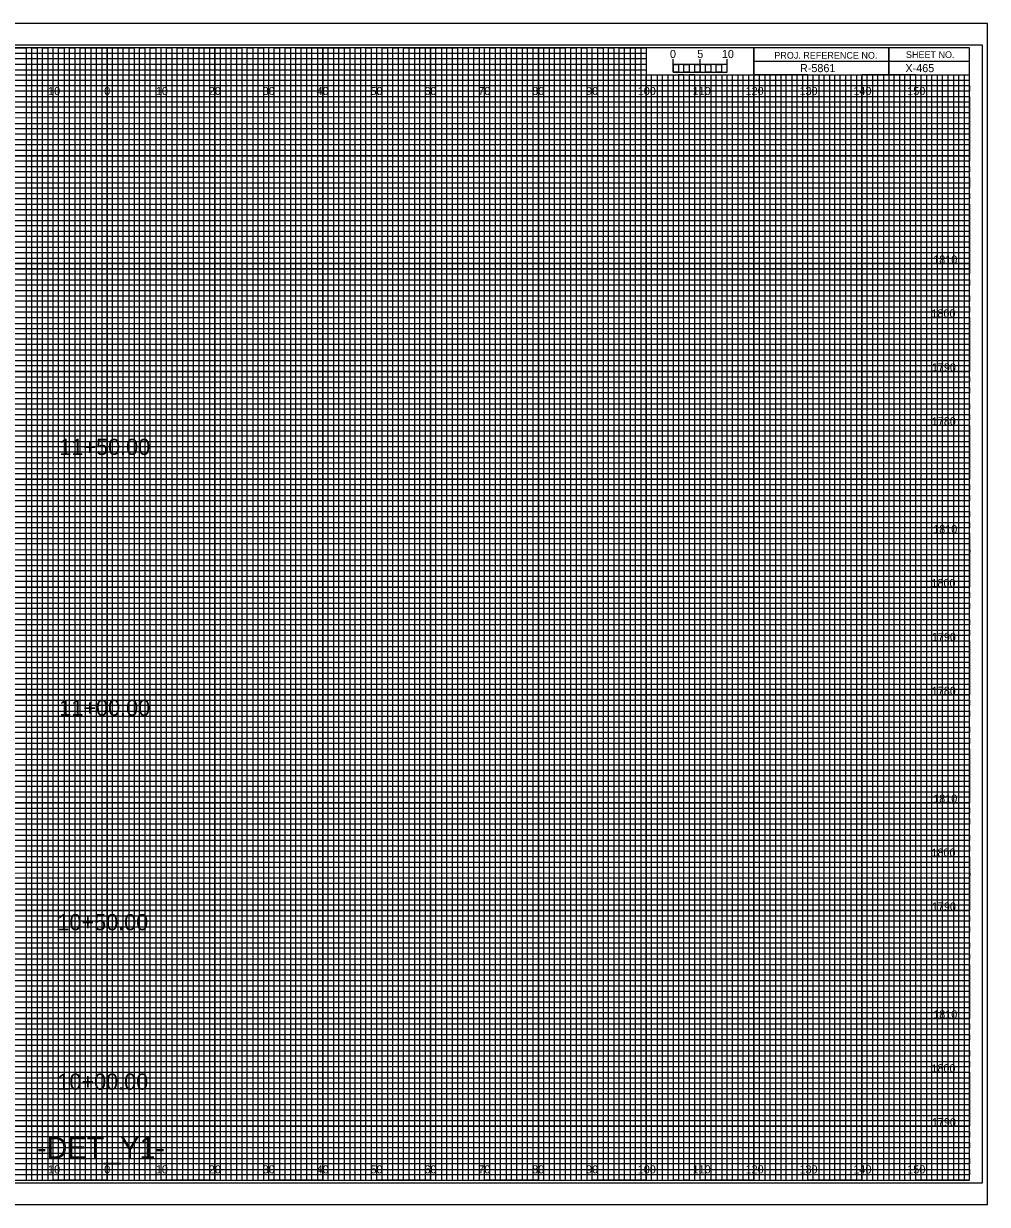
# Model space of a CAD drawing. Extents: x -13 to 323, y -5 to 434.
# Drawn here: x 144.5 to 323.3, y -4.5 to 214.5 of the extents above; entities that cross this region are included whole.
import ezdxf

# ---------------------------------------------------------------- set-up
doc = ezdxf.new("R2010")
doc.units = 0
for name, color, linetype in [('Old_Level_1', 7, 'Continuous'), ('Old_Level_62', 7, 'Continuous'), ('Pattern 1', 7, 'Continuous'), ('Pattern 18', 7, 'Continuous'), ('Pattern 4', 7, 'Continuous'), ('Pattern 5', 7, 'Continuous'), ('Prop Dimension', 7, 'Continuous'), ('Prop Horizontal Alignment', 7, 'Continuous'), ('Prop PHM Label Text', 7, 'Continuous'), ('Prop PHM Label Text White', 7, 'Continuous'), ('Prop PHM Roadway Shape', 7, 'Continuous'), ('Prop PHM White Shape', 7, 'Continuous'), ('Scratch_Level_0', 7, 'Continuous'), ('Scratch_Level_2', 7, 'Continuous'), ('Scratch_Level_3', 7, 'Continuous'), ('Scratch_Level_5', 7, 'Continuous'), ('Scratch_Level_6', 7, 'Continuous')]:
    doc.layers.add(name, color=color, linetype=linetype)

msp = doc.modelspace()

# ---------------------------------------------------------------- linework, layer by layer
at = {"layer": 'Old_Level_62'}
for p, q in [((0, 209), (260, 209)), ((260, 209), (260, 207.98)), ((260, 207.98), (0, 207.98)), ((0, 207), (260, 207)), ((260, 205.89), (0, 205.89)), ((260, 207), (260, 205.89)), ((0, 204), (320, 204))]:
    msp.add_line(p, q, dxfattribs=at)
for points in [[(0, 203), (270, 203), (320, 203), (320, 202), (0, 202)], [(0, 201), (320, 201), (320, 199), (0, 199)], [(0, 198), (320, 198), (320, 197), (0, 196.98)], [(0, 196), (320, 196), (320, 194), (0, 194)], [(0, 193), (320, 193), (320, 192), (0, 192)], [(0, 191), (320, 191), (320, 189), (0, 189)], [(0, 188), (320, 188), (320, 187), (0, 187)], [(0, 186), (320, 186), (320, 184), (0, 184)], [(0, 183), (320, 183), (320, 182), (0, 182)], [(0, 181), (320, 181), (320, 179), (0, 179)], [(0, 178), (320, 178), (320, 177), (0, 177)], [(0, 176), (320, 176), (320, 173.95), (320, 173), (320, 172), (0, 172)], [(0, 174), (320, 174), (320, 173), (0, 173)], [(0, 171), (320, 171), (320, 169), (0, 169.03)], [(0, 169.03), (320, 169), (320, 168), (0, 168)], [(0, 167), (320, 167), (320, 166), (0, 166)], [(0, 164), (320, 164), (320, 163), (0, 163)], [(0, 162), (320, 162), (320, 161), (0, 161)], [(-0.07, 158.89), (320, 158.89), (320, 157.88), (-0.07, 157.88)], [(0, 157), (320, 157), (320, 156), (0, 156)], [(0, 154), (320, 154), (320, 153), (0, 153)], [(0, 152), (320, 152), (320, 151), (0, 151)], [(0, 149), (320, 149), (320, 148), (0, 148)], [(0, 147), (320, 147), (320, 146), (0, 146)], [(0, 144), (320, 144), (320, 143), (0, 143)], [(0, 142), (320, 142), (320, 141), (0, 141)], [(0, 139), (320, 139), (319.99, 137.98), (0, 138)], [(0, 137), (320, 137), (320, 136), (0, 136)], [(0, 134), (320, 134), (320, 133), (0, 133)], [(0, 132), (320, 132), (320, 131), (0, 131)], [(0, 129), (320, 129), (320, 128), (0, 128)], [(0, 127), (320, 127), (320, 126), (0, 126)], [(0, 124), (320, 124), (320, 123), (0, 123)], [(0, 122), (320, 122), (320, 121), (0, 121)], [(0, 119), (320, 119), (320, 118), (0, 118)], [(0, 116.99), (320.07, 116.91), (320, 116), (0, 116)], [(0, 114), (320, 114), (320, 113), (0, 113)], [(0, 112), (320, 112), (320, 111), (0, 111)], [(0, 109), (320, 109), (320, 108), (0, 108)], [(0, 107), (320, 107), (320, 106), (0, 106)], [(0, 104), (320, 104), (320, 103), (0, 103)], [(0, 102), (320, 102), (320, 101), (0, 101)], [(0, 99), (320, 99), (320, 98), (0, 98)], [(0, 97), (320, 97), (320, 96), (0, 96)], [(0, 94), (320, 94), (320, 93), (0, 93)], [(0, 92), (320, 92), (320, 91), (0, 91)], [(0, 89), (320, 89), (320, 88), (0, 88)], [(0, 87), (320, 87), (320, 86), (0, 86)], [(0, 84), (320, 84), (320, 83), (0, 83)], [(0, 82), (320, 82), (320, 81), (0, 81)], [(0, 79), (320, 79), (319.99, 77.98), (0, 78)], [(0, 77), (320, 77), (320, 76), (0, 76)], [(0, 74), (320, 74), (320, 73), (0, 73)], [(0, 72), (320, 72), (320, 71), (0, 71)], [(0, 69), (320, 69), (320, 68), (0, 68)], [(0, 67), (320, 67), (320, 66), (0, 66)], [(0, 64), (320, 64), (320, 63), (0, 63)], [(0, 62), (320, 62), (320, 61), (0, 61)], [(0, 59), (320, 59), (320, 58), (0, 58)], [(0, 56.99), (320.07, 56.91), (320, 56), (0, 56)], [(0, 54), (320, 54), (320, 53), (0, 53)], [(0, 52), (320, 52), (320, 51), (0, 51)], [(0, 49), (320, 49), (320, 48), (0, 48)], [(0, 47), (320, 47), (320, 46), (0, 46)], [(0, 44), (320, 44), (320, 43), (0, 43)], [(0, 42), (320, 42), (320, 41), (0, 41)], [(0, 39), (320, 39), (320, 38), (0, 38)], [(0, 37), (320, 37), (320, 36), (0, 36)], [(0, 34), (320, 34), (320, 33), (0, 33)], [(0, 32), (320, 32), (320, 31), (0, 31)], [(0, 29), (320, 29), (320, 28), (0, 28)], [(0, 27), (320, 27), (320, 26), (0, 26)], [(0, 24), (320, 24), (320, 23), (0, 23)], [(0, 22), (320, 22), (320, 21), (0, 21)], [(0, 19), (320, 19), (320, 18), (0, 18)], [(0, 17), (320, 17), (320, 16), (0, 16)], [(0, 14), (320, 14), (320, 13), (0, 13)], [(0, 12), (320, 12), (320, 11), (0, 11)], [(0, 9), (320, 9), (320, 8), (0, 8)], [(0, 7), (320, 7), (320, 6), (0, 6)], [(0, 4), (320, 4), (320, 3), (0, 3)], [(0, 2), (320, 2), (320, 1), (0, 1)]]:
    msp.add_lwpolyline(points, dxfattribs=at)
at = {"layer": 'Pattern 1'}
for p, q in [((323.3, 214.5), (-13.4, 214.5)), ((-13.4, -4.5), (323.3, -4.5))]:
    msp.add_line(p, q, dxfattribs=at)
at = {"layer": 'Pattern 18'}
for p, q in [((265, 205.49), (265, 207.9)), ((265, 206.9), (265, 207.9)), ((270, 205.49), (270, 207.9)), ((275, 205.49), (275, 207.9)), ((275, 206.9), (275, 207.9))]:
    msp.add_line(p, q, dxfattribs=at)
for points in [[(275, 206.9), (265, 206.9), (265, 205.49), (275, 205.49)], [(265, 206.9), (266, 206.9), (266, 205.49), (265, 205.49)], [(267, 206.9), (268, 206.9), (268, 205.49), (267, 205.49)], [(269, 206.9), (270, 206.9), (270, 205.49), (269, 205.49)], [(271, 206.9), (272, 206.9), (272, 205.49), (271, 205.49)], [(273, 206.9), (274, 206.9), (274, 205.49), (273, 205.49)]]:
    msp.add_lwpolyline(points, close=True, dxfattribs=at)
at = {"layer": 'Pattern 4'}
for points in [[(135, 210), (145, 210), (145, 0), (155, 0), (155, 210), (165, 210), (165, 0), (175, 0), (175, 210), (185, 210), (185, 0), (195, 0), (195, 210), (205, 210), (205, 0), (215, 0), (215, 210), (225, 210), (225, 0), (235, 0), (235, 210), (245, 210), (245, 0), (255, 0), (255, 210), (259.93, 210), (260, 210), (260, 205), (264.99, 205), (264.99, 0), (275, 0), (275, 205), (285, 205), (285, 0), (295, 0), (295, 205), (305, 205), (305, 0), (315, 0), (315, 205)], [(0, 205), (275, 205)], [(0, 185), (320, 185), (320, 195), (0, 195)], [(0, 165), (320, 165), (320, 175), (0, 175)], [(0, 145), (320, 145), (320, 155), (0, 155)], [(0, 125), (320, 125), (320, 135), (0, 135)], [(0, 105), (320, 105), (320, 115), (0, 115)], [(0, 85), (320, 85), (320, 95), (0, 95)], [(0, 65), (320, 65), (320, 75), (0, 75)], [(0, 45), (320, 45), (320, 55), (0, 55)], [(0, 25), (320, 25), (320, 35), (0, 35)], [(0, 5), (320, 5), (320, 15), (0, 15)]]:
    msp.add_lwpolyline(points, dxfattribs=at)
at = {"layer": 'Pattern 5'}
for p, q in [((150, 0), (150, 210)), ((160, 0), (160, 210)), ((170, 0), (170, 210)), ((180, 0), (180, 210)), ((190, 0), (190, 210)), ((200, 0), (200, 210)), ((210, 0), (210, 210)), ((220, 0), (220, 210)), ((230, 0), (230, 210)), ((240, 0), (240, 210)), ((250, 0), (250, 210)), ((260, 0), (260, 204.69)), ((270, 0), (270, 204.69)), ((280, 0), (280, 204.69)), ((290, 0), (290, 204.69)), ((300, 0), (300, 204.69)), ((310, 0), (310, 204.69)), ((0, 200), (320, 200)), ((0, 190), (320, 190)), ((0, 180), (320, 180)), ((0, 170), (320, 170)), ((0, 160), (320, 160)), ((0, 150), (320, 150)), ((0, 140), (320, 140)), ((0, 130), (320, 130)), ((0, 120), (320, 120)), ((0, 110), (320, 110)), ((0, 100), (320, 100)), ((0, 90), (320, 90)), ((0, 80), (320, 80)), ((0, 70), (320, 70)), ((0, 60), (320, 60)), ((0, 50), (320, 50)), ((0, 40), (320, 40)), ((0, 30), (320, 30)), ((0, 20), (320, 20)), ((0, 10), (320, 10))]:
    msp.add_line(p, q, dxfattribs=at)
at = {"layer": 'Prop Dimension'}
for p, q in [((305, 210), (305, 205)), ((305, 205), (305, 210)), ((280, 207.5), (280, 205)), ((320, 207.49), (280, 207.49)), ((280, 205), (320, 205))]:
    msp.add_line(p, q, dxfattribs=at)
for points in [[(320, 210), (0, 210), (0, 0), (320, 0)], [(280, 210), (260, 210), (260, 205.03), (280, 205.03)], [(320, 210), (280, 210), (280, 205), (320, 205)]]:
    msp.add_lwpolyline(points, close=True, dxfattribs=at)
at = {"layer": 'Prop Horizontal Alignment'}
for p, q in [((150, 210), (140, 210)), ((150, 0), (150, 210)), ((170, 210), (160, 210)), ((160, 210), (160, 0)), ((170, 0), (170, 210)), ((190, 210), (180, 210)), ((180, 210), (180, 0)), ((190, 0), (190, 210)), ((210, 210), (200, 210)), ((200, 210), (200, 0)), ((210, 0), (210, 210)), ((230, 210), (220, 210)), ((220, 210), (220, 0)), ((230, 0), (230, 210)), ((250, 210), (240, 210)), ((240, 210), (240, 0)), ((250, 0), (250, 210)), ((260, 210), (260, 0)), ((270, 0), (270, 205)), ((290, 205), (280, 205)), ((280, 205), (280, 0)), ((290, 0), (290, 205)), ((310, 205), (300, 205)), ((300, 205), (300, 0)), ((310, 0), (310, 205)), ((160, 0), (150, 0)), ((180, 0), (170, 0)), ((200, 0), (190, 0)), ((220, 0), (210, 0)), ((240, 0), (230, 0)), ((260, 0), (250, 0)), ((280, 0), (270, 0)), ((300, 0), (290, 0)), ((320, 0), (310, 0)), ((320, 0), (320, 0))]:
    msp.add_line(p, q, dxfattribs=at)
for points in [[(0, 200), (320, 200), (320, 190), (0, 190)], [(0, 180), (320, 180), (320, 170), (0, 170)], [(0, 160), (320, 160), (320, 150), (0, 150)], [(0, 140), (320, 140), (320, 130), (0, 130)], [(0, 120), (320, 120), (320, 110), (0, 110)], [(0, 100), (320, 100), (320, 90), (0, 90)], [(0, 80), (320, 80), (320, 70), (0, 70)], [(0, 60), (320, 60), (320, 50), (0, 50)], [(0, 40), (320, 40), (320, 30), (0, 30)], [(0, 20), (320, 20), (320, 10), (0, 10)]]:
    msp.add_lwpolyline(points, dxfattribs=at)
at = {"layer": 'Prop PHM Label Text'}
for p, q in [((267, 205), (266.01, 205)), ((266.01, 205), (266.01, 0)), ((267, 0), (267, 205)), ((269, 205), (268, 205)), ((268, 205), (268, 0)), ((269, 0), (269, 205)), ((266.01, 0), (265, 0)), ((268, 0), (267, 0))]:
    msp.add_line(p, q, dxfattribs=at)
for points in [[(145, 0), (146, 0), (146, 210), (147, 210), (147, 0)], [(147, 0), (148, 0), (148, 210), (149, 210), (149, 0)], [(150, 0), (151, 0), (151, 210), (152, 210), (152, 0)], [(152, 0), (153, 0), (153, 210), (154, 210), (154, 0)], [(155, 0), (156, 0), (156, 210), (157, 210), (157, 0)], [(157, 0), (158, 0), (158, 210), (159, 210), (159, 0)], [(160, 0), (161, 0), (161, 210), (162, 210), (162, 0)], [(162, 0), (163, 0), (163, 210), (164, 210), (164, 0)], [(165, 0), (166, 0), (166, 210), (167, 210), (167, 0)], [(167, 0), (168, 0), (168, 210), (169, 210), (169, 0)], [(170, 0), (171, 0), (171, 210), (172, 210), (172, 0)], [(172, 0), (173, 0), (173, 210), (174, 210), (174, 0)], [(175, 0), (176, 0), (176, 210), (177, 210), (177, 0)], [(177, 0), (178, 0), (178, 210), (179, 210), (179, 0)], [(180, 0), (181, 0), (181, 210), (182, 210), (182, 0)], [(182, 0), (183, 0), (183, 210), (184, 210), (184, 0)], [(185, 0), (186, 0), (186, 210), (187, 210), (187, 0)], [(187, 0), (188, 0), (188, 210), (189, 210), (189, 0)], [(190, 0), (191, 0), (191, 210), (192, 210), (192, 0)], [(192, 0), (193, 0), (193, 210), (194, 210), (194, 0)], [(195, 0), (196, 0), (196, 210), (197, 210), (197, 0)], [(197, 0), (198, 0), (198, 210), (199, 210), (199, 0)], [(200, 0), (201, 0), (201, 210), (202, 210), (202, 0)], [(202, 0), (203, 0), (203, 210), (204, 210), (204, 0)], [(205, 0), (206, 0), (206, 210), (207, 210), (207, 0)], [(207, 0), (208, 0), (208, 210), (209, 210), (209, 0)], [(210, 0), (211, 0), (211, 210), (212, 210), (212, 0)], [(212, 0), (213, 0), (213, 210), (214, 210), (214, 0)], [(215, 0), (216, 0), (216, 210), (217, 210), (217, 0)], [(217, 0), (218, 0), (218, 210), (219, 210), (219, 0)], [(220, 0), (221, 0), (221, 210), (222, 210), (222, 0)], [(222, 0), (223, 0), (223, 210), (224, 210), (224, 0)], [(225, 0), (226, 0), (226, 210), (227, 210), (227, 0)], [(227, 0), (228, 0), (228, 210), (229, 210), (229, 0)], [(230, 0), (231, 0), (231, 210), (232, 210), (232, 0)], [(232, 0), (233, 0), (233, 210), (234, 210), (234, 0)], [(235, 0), (236, 0), (236, 210), (237, 210), (237, 0)], [(237, 0), (238, 0), (238, 210), (239, 210), (239, 0)], [(240, 0), (241, 0), (241, 210), (242, 210), (242, 0)], [(242, 0), (243, 0), (243, 210), (244, 210), (244, 0)], [(245, 0), (246, 0), (246, 210), (247, 210), (247, 0)], [(247, 0), (248, 0), (248, 210), (249, 210), (249, 0)], [(250, 0), (251, 0), (251, 210), (252, 210), (252, 0)], [(252, 0), (253, 0), (253, 210), (254, 210), (254, 0)], [(255, 0), (256, 0), (256, 210), (257, 210), (257, 0)], [(257, 0), (258, 0), (258, 210), (259, 210), (259, 0)], [(260, 0), (261, 0), (261, 205), (262.02, 205), (262.02, 0)], [(262, 0), (263, 0), (263, 205), (263.99, 205), (263.99, 0)], [(270, 0), (270.98, 0), (270.98, 205), (272, 205), (272, 0)], [(272, 0), (273, 0), (273, 205), (274.05, 205), (274.05, 0)], [(275, 0), (276, 0), (276, 205), (277, 205), (277, 0)], [(277, 0), (278, 0), (278, 205), (279, 205), (279, 0)], [(280, 0), (281, 0), (281, 205), (282, 205), (282, 0)], [(282, 0), (283, 0), (283, 205), (284, 205), (284, 0)], [(285, 0), (286, 0), (286, 205), (287, 205), (287, 0)], [(287, 0), (288, 0), (288, 205), (289, 205), (289, 0)], [(290, 0), (291, 0), (291, 205), (292, 205), (292, 0)], [(292, 0), (293, 0), (293, 205), (294, 205), (294, 0)], [(295, 0), (296, 0), (296, 205), (297, 205), (297, 0)], [(297, 0), (298, 0), (298, 205), (299, 205), (299, 0)], [(300, 0), (301, 0), (301, 205), (302, 205), (302, 0)], [(302, 0), (303, 0), (303, 205), (304, 205), (304, 0)], [(305, 0), (306, 0), (306, 205), (307, 205), (307, 0)], [(307, 0), (308, 0), (308, 205), (309, 205), (309, 0)], [(310, 0), (311, 0), (311, 205), (312, 205), (312, 0)], [(312, 0), (313, 0), (313, 205), (314, 205), (314, 0)], [(315, 0), (316, 0), (316, 205), (317, 205), (317, 0)], [(317, 0), (318, 0), (318, 205), (319, 205), (319, 0)]]:
    msp.add_lwpolyline(points, dxfattribs=at)
at = {"layer": 'Scratch_Level_0'}
msp.add_lwpolyline([(-10.8, -0.5), (322.4, -0.5), (322.4, 210.5), (-10.8, 210.5)], close=True, dxfattribs=at)
at = {"layer": 'Scratch_Level_5'}
msp.add_lwpolyline([(-13.4, -4.5), (323.3, -4.5), (323.3, 214.5), (-13.4, 214.5)], close=True, dxfattribs=at)

# ---------------------------------------------------------------- texts
at = {"layer": 'Old_Level_1'}
msp.add_text('-DET_Y1-', height=4, dxfattribs=at).set_placement((146.97, 4))
at = {"layer": 'Pattern 18'}
msp.add_text('0', height=1.5, dxfattribs=at).set_placement((264.41, 208.12))
at = {"layer": 'Prop Dimension'}
for s, p in [('PROJ. REFERENCE NO.', (283.77, 207.99)), ('SHEET NO.', (308.19, 208.12))]:
    msp.add_text(s, height=1.25, dxfattribs=at).set_placement(p)
at = {"layer": 'Prop PHM Label Text White'}
for s, p in [('11+50.00', (151.13, 134.5)), ('11+00.00', (151.13, 86.11)), ('10+50.00', (150.77, 46.34)), ('10+00.00', (150.77, 16.77))]:
    msp.add_text(s, height=3, dxfattribs=at).set_placement(p)
at = {"layer": 'Prop PHM Roadway Shape'}
msp.add_text('X-465', height=1.5, dxfattribs=at).set_placement((308.09, 205.5))
at = {"layer": 'Prop PHM White Shape'}
msp.add_text('R-5861', height=1.5, dxfattribs=at).set_placement((288.53, 205.5))
at = {"layer": 'Scratch_Level_2'}
for s, p in [('1810', (313.25, 170)), ('1800', (312.92, 160)), ('1790', (313, 150)), ('1780', (312.98, 140)), ('1810', (313.25, 120)), ('1800', (312.92, 110)), ('1790', (313, 100)), ('1780', (312.98, 90)), ('1810', (313.25, 70)), ('1800', (312.92, 60)), ('1790', (313, 50)), ('1810', (313.25, 30)), ('1800', (312.92, 20)), ('1790', (313, 10))]:
    msp.add_text(s, height=1.5, dxfattribs=at).set_placement(p)
at = {"layer": 'Scratch_Level_3'}
for s, p in [('10', (149.04, 201.25)), ('0', (159.45, 201.25)), ('0', (159.45, 201.25)), ('10', (169.04, 201.25)), ('20', (178.86, 201.25)), ('30', (188.86, 201.25)), ('40', (198.86, 201.25)), ('50', (208.86, 201.25)), ('60', (218.86, 201.25)), ('70', (228.86, 201.25)), ('80', (238.86, 201.25)), ('90', (248.86, 201.25)), ('100', (258.44, 201.25)), ('110', (268.62, 201.25)), ('120', (278.44, 201.25)), ('130', (288.44, 201.25)), ('140', (298.44, 201.25)), ('150', (308.44, 201.25)), ('10', (149.04, 1.25)), ('0', (159.45, 1.25)), ('0', (159.45, 1.25)), ('10', (169.04, 1.25)), ('20', (178.86, 1.25)), ('30', (188.86, 1.25)), ('40', (198.86, 1.25)), ('50', (208.86, 1.25)), ('60', (218.86, 1.25)), ('70', (228.86, 1.25)), ('80', (238.86, 1.25)), ('90', (248.86, 1.25)), ('100', (258.44, 1.25)), ('110', (268.62, 1.25)), ('120', (278.44, 1.25)), ('130', (288.44, 1.25)), ('140', (298.44, 1.25)), ('150', (308.44, 1.25))]:
    msp.add_text(s, height=1.5, dxfattribs=at).set_placement(p)
at = {"layer": 'Scratch_Level_6'}
for s, p in [('5', (269.47, 208.12)), ('10', (274.04, 208.12))]:
    msp.add_text(s, height=1.5, dxfattribs=at).set_placement(p)

doc.saveas('drawing.dxf')
